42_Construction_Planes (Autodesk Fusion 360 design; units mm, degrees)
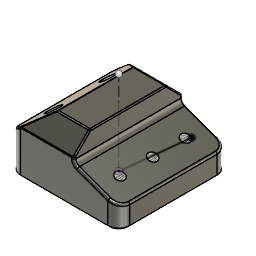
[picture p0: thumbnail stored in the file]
part number: 2026-07-20-09-52-29-073
sketch "Sketch1" plane through (0, 0, 0) normal (0, 1, 0) x axis (1, 0, 0)
  line L1 (-50, 0) -> (0, 0)
  line L2 (-50, -32.5203) -> (-50, 0)
  line L3 (-21.2122, -55) -> (-50, -32.5203)
  line L4 (8.7878, -55) -> (-21.2122, -55)
  line L5 (8.7878, -35) -> (8.7878, -55)
  line L6 (50, -20) -> (8.7878, -35)
  line L7 (50, 0) -> (50, -20)
  line L8 (0, 0) -> (50, 0)
  point P1 (0, 0)
  point P2 (0, 0)
  point P7 (8.7878, -35)
  point P5 (-21.2122, -55)
  point P8 (50, -20)
  coincident P1 P2
  horizontal L1
  perpendicular L1 L2
  perpendicular L2 L4
  perpendicular L4 L5
  perpendicular L4 L7
  perpendicular L7 L8
  equal L1 L8
  dimension "d1" distance L1 P7 = 35
  dimension "d2" distance L2 L7 = 100
  dimension "d3" distance L4 L8 = 55
  dimension "d4" angle L6 L7 = 110
  dimension "d5" angle L2 L3 = 127.985
  dimension "d6" distance P5 L5 = 30
  dimension "d7" distance L1 P8 = 20
extrude "Extrude1" new body sketch "Sketch1" distance 100
chamfer "Chamfer1" distance 15
sketch "Sketch2" plane through (-34.7148, 0, 44.4561) normal (-0.6155, 0, 0.7882) x axis (0, -1, 0)
  line L1 (-50, -7.2403) -> (-35, 17.1316)
  line L2 (-50, -19.3934) -> (-50, -7.2403)
  line L3 (50, -19.3934) -> (-50, -19.3934)
  line L4 (50, -7.2403) -> (50, -19.3934)
  line L5 (35, 17.1316) -> (50, -7.2403)
  line L6 (-35, 17.1316) -> (35, 17.1316)
  point P1 (0, 0)
  point P8 (-25, 0)
  point P9 (25, 0)
  horizontal P1 P8
  horizontal P1 P9
  dimension "d12" distance P1 P8 = 25
  dimension "d13" distance P1 P9 = 25 (= "d12")
hole "Hole1" HoleDepth 25 HoleDiameter 13.526 TipAngle 118
sketch "Sketch3" plane through (12.2768, 0, 33.7301) normal (0.342, 0, 0.9397) x axis (0, 1, 0)
  line L1 (50, -40.1442) -> (-50, -40.1442)
  line L2 (50, 3.7128) -> (50, -40.1442)
  line L3 (-50, 3.7128) -> (50, 3.7128)
  line L4 (-50, -40.1442) -> (-50, 3.7128)
  point P6 (-30, -20)
  point P7 (0, -20)
  point P8 (30, -20)
  point P1 (0, 0)
  horizontal P6 P7
  horizontal P7 P8
  vertical P1 P7
  dimension "d19" distance P1 P7 = 20
  dimension "d20" distance P6 P7 = 30
  dimension "d21" distance P7 P8 = 30 (= "d20")
hole "Hole2" HoleDepth 15 HoleDiameter 8.526 TipAngle 118
fillet "Fillet1" radius 10
fillet "Fillet2" radius 5
fillet "Fillet3" radius 2
fillet "Fillet4" radius 1
fillet "Fillet5" radius 1
sketch "Sketch4" plane through (0, 0, 0) normal (0, 0, -1) x axis (1, 0, 0)
  line L1 (50, 40) -> (50, -40)
  line L2 (-40, 50) -> (40, 50)
  line L3 (-50, -40) -> (-50, 40)
  line L4 (40, -50) -> (-40, -50)
  arc A1 centre (40, -40) radius 10 clockwise from (50, -40) to (40, -50)
  arc A2 centre (40, 40) radius 10 clockwise from (40, 50) to (50, 40)
  arc A3 centre (-40, 40) radius 10 clockwise from (-50, 40) to (-40, 50)
  arc A4 centre (-40, -40) radius 10 clockwise from (-40, -50) to (-50, -40)
  point P10 (-40, 40)
  point P14 (-40, 40)
  point P7 (40, 40)
  point P15 (40, 40)
  point P4 (40, -40)
  point P16 (40, -40)
  point P13 (-40, -40)
  point P17 (-40, -40)
  coincident P10 P14
  coincident P7 P15
  coincident P4 P16
  coincident P13 P17
hole "Hole3" HoleDepth 15 HoleDiameter 8.526 TipAngle 118
chamfer "Chamfer2" distance 2
sketch "Sketch5" plane through (0, 0, 0) normal (0, 1, 0) x axis (1, 0, 0)
  line L1 (0, -77.2881) -> (0, 0)
  line L2 (66.883, -60.2218) -> (0, 0)
  point P1 (0, 0)
  point P2 (0, 0)
  point P4 (66.883, -60.2218)
  coincident P1 P2
  vertical L1
  dimension "d43" angle L1 L2 = 48
  dimension "d44" distance P2 P4 = 90
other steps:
thread "Thread1" ThreadOffset 0 ThreadDepth 7.4
thread "Thread2" ThreadOffset 0 ThreadDepth 7.4
thread "Thread3" ThreadOffset 0 ThreadDepth 7.4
